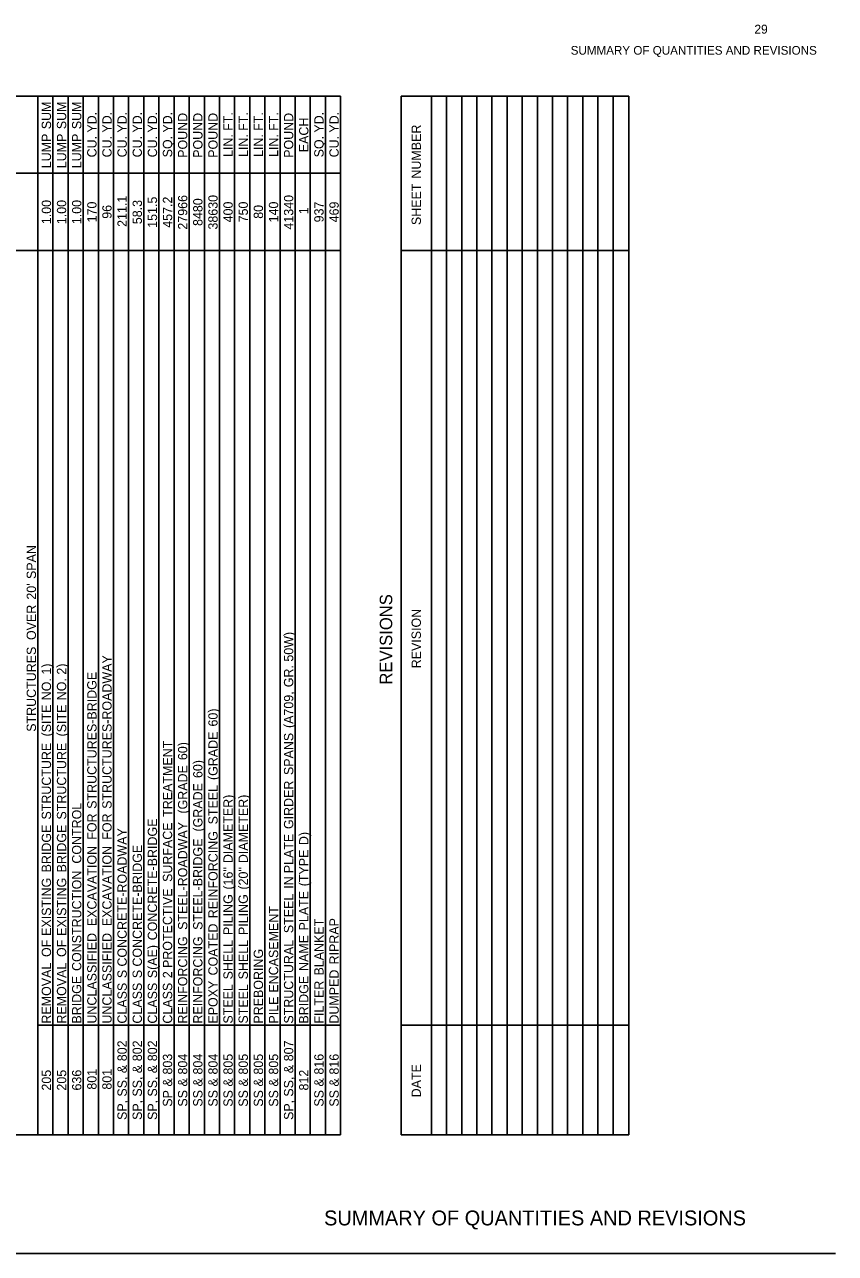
# Model space of a CAD drawing. Extents: x 1334737.6 to 1334769.2, y 402732.2 to 402752.
# Drawn here: x 1334756.13 to 1334769.18, y 402732.19 to 402751.98 of the extents above; entities that cross this region are included whole.
import ezdxf

# ---------------------------------------------------------------- set-up
doc = ezdxf.new("R2010")
doc.units = 0
doc.layers.add('Default', color=7, linetype='Continuous')
doc.layers.add('R_No Plot', color=7, linetype='Continuous')

msp = doc.modelspace()

# ---------------------------------------------------------------- linework, layer by layer
at = {"layer": 'Default'}
for p, q in [((1334761.215, 402750.83), (1334740.008, 402750.83)), ((1334756.34, 402734.097), (1334756.34, 402750.83)), ((1334756.583, 402734.097), (1334756.583, 402750.83)), ((1334756.827, 402734.097), (1334756.827, 402750.83)), ((1334757.071, 402734.097), (1334757.071, 402750.83)), ((1334757.315, 402734.097), (1334757.315, 402750.83)), ((1334757.558, 402734.097), (1334757.558, 402750.83)), ((1334757.802, 402734.097), (1334757.802, 402750.83)), ((1334758.046, 402734.097), (1334758.046, 402750.83)), ((1334758.29, 402734.097), (1334758.29, 402750.83)), ((1334758.533, 402734.097), (1334758.533, 402750.83)), ((1334758.777, 402734.097), (1334758.777, 402750.83)), ((1334759.021, 402734.097), (1334759.021, 402750.83)), ((1334759.265, 402734.097), (1334759.265, 402750.83)), ((1334759.508, 402734.097), (1334759.508, 402750.83)), ((1334759.752, 402734.097), (1334759.752, 402750.83)), ((1334759.996, 402734.097), (1334759.996, 402750.83)), ((1334760.24, 402734.097), (1334760.24, 402750.83)), ((1334760.483, 402734.097), (1334760.483, 402750.83)), ((1334760.727, 402734.097), (1334760.727, 402750.83)), ((1334760.971, 402734.097), (1334760.971, 402750.83)), ((1334761.215, 402734.097), (1334761.215, 402750.83)), ((1334762.19, 402734.097), (1334762.19, 402750.83)), ((1334762.19, 402748.344), (1334762.19, 402750.83)), ((1334765.858, 402750.83), (1334762.19, 402750.83)), ((1334762.677, 402734.097), (1334762.677, 402750.83)), ((1334762.921, 402734.097), (1334762.921, 402750.83)), ((1334763.165, 402734.097), (1334763.165, 402750.83)), ((1334763.408, 402734.097), (1334763.408, 402750.83)), ((1334763.652, 402734.097), (1334763.652, 402750.83)), ((1334763.896, 402734.097), (1334763.896, 402750.83)), ((1334764.14, 402734.097), (1334764.14, 402750.83)), ((1334764.383, 402734.097), (1334764.383, 402750.83)), ((1334764.627, 402734.097), (1334764.627, 402750.83)), ((1334764.871, 402734.097), (1334764.871, 402750.83)), ((1334765.115, 402734.097), (1334765.115, 402750.83)), ((1334765.358, 402734.097), (1334765.358, 402750.83)), ((1334765.602, 402734.097), (1334765.602, 402750.83)), ((1334765.858, 402734.097), (1334765.858, 402750.83)), ((1334761.215, 402749.587), (1334740.008, 402749.587)), ((1334761.215, 402749.587), (1334756.34, 402749.587)), ((1334761.215, 402748.344), (1334740.008, 402748.344)), ((1334761.215, 402748.344), (1334756.34, 402748.344)), ((1334762.677, 402748.344), (1334762.19, 402748.344)), ((1334765.858, 402748.344), (1334762.19, 402748.344)), ((1334757.071, 402735.864), (1334756.34, 402735.864)), ((1334761.215, 402735.864), (1334756.34, 402735.864)), ((1334762.19, 402734.097), (1334762.19, 402735.864)), ((1334765.858, 402735.864), (1334762.19, 402735.864)), ((1334761.215, 402734.097), (1334740.008, 402734.097)), ((1334765.858, 402734.097), (1334762.19, 402734.097))]:
    msp.add_line(p, q, dxfattribs=at)
at = {"layer": 'R_No Plot'}
msp.add_line((1334769.182, 402732.187), (1334737.564, 402732.187), dxfattribs=at)

# ---------------------------------------------------------------- texts
at = {"layer": 'Default'}
for s, height, p in [(' SUM', 0.15, (1334756.553, 402750.241)), (' SUM', 0.15, (1334756.797, 402750.241)), (' SUM', 0.15, (1334757.041, 402750.241)), (' YD.', 0.15, (1334757.285, 402750.186)), (' YD.', 0.15, (1334757.528, 402750.186)), (' YD.', 0.15, (1334757.772, 402750.186)), (' YD.', 0.15, (1334758.016, 402750.186)), (' YD.', 0.15, (1334758.26, 402750.186)), (' YD.', 0.15, (1334758.503, 402750.186)), ('POUND', 0.15, (1334758.747, 402749.836)), ('POUND', 0.15, (1334758.991, 402749.836)), ('POUND', 0.15, (1334759.235, 402749.836)), (' FT.', 0.15, (1334759.478, 402750.215)), (' FT.', 0.15, (1334759.722, 402750.215)), (' FT.', 0.15, (1334759.966, 402750.215)), (' FT.', 0.15, (1334760.21, 402750.215)), ('POUND', 0.15, (1334760.453, 402749.836)), (' YD.', 0.15, (1334760.941, 402750.186)), (' YD.', 0.15, (1334761.185, 402750.186)), ('EACH', 0.15, (1334760.697, 402749.926)), (' NUMBER', 0.15, (1334762.508, 402749.446)), ('LUMP', 0.15, (1334756.553, 402749.668)), ('LUMP', 0.15, (1334756.797, 402749.668)), ('LUMP', 0.15, (1334757.041, 402749.668)), ('CU.', 0.15, (1334757.285, 402749.843)), ('CU.', 0.15, (1334757.528, 402749.843)), ('CU.', 0.15, (1334757.772, 402749.843)), ('CU.', 0.15, (1334758.016, 402749.843)), ('CU.', 0.15, (1334758.26, 402749.843)), ('SQ.', 0.15, (1334758.503, 402749.843)), ('LIN.', 0.15, (1334759.478, 402749.849)), ('LIN.', 0.15, (1334759.722, 402749.849)), ('LIN.', 0.15, (1334759.966, 402749.849)), ('LIN.', 0.15, (1334760.21, 402749.849)), ('SQ.', 0.15, (1334760.941, 402749.843)), ('CU.', 0.15, (1334761.185, 402749.843)), ('SHEET', 0.15, (1334762.508, 402748.752)), ('211.1', 0.15, (1334757.772, 402748.723)), ('151.5', 0.15, (1334758.26, 402748.708)), ('457.2', 0.15, (1334758.503, 402748.709)), ('27966', 0.15, (1334758.747, 402748.679)), ('8480', 0.15, (1334758.991, 402748.738)), ('38630', 0.15, (1334759.235, 402748.68)), ('41340', 0.15, (1334760.453, 402748.68)), ('1.00', 0.15, (1334756.553, 402748.767)), ('1.00', 0.15, (1334756.797, 402748.767)), ('1.00', 0.15, (1334757.041, 402748.767)), ('170', 0.15, (1334757.285, 402748.796)), ('96', 0.15, (1334757.528, 402748.854)), ('58.3', 0.15, (1334758.016, 402748.767)), ('400', 0.15, (1334759.478, 402748.796)), ('750', 0.15, (1334759.722, 402748.796)), ('80', 0.15, (1334759.966, 402748.854)), ('140', 0.15, (1334760.21, 402748.796)), ('1', 0.15, (1334760.697, 402748.927)), ('937', 0.15, (1334760.941, 402748.796)), ('469', 0.15, (1334761.185, 402748.796)), (' SPAN', 0.15, (1334756.31, 402742.995)), (" 20'", 0.15, (1334756.31, 402742.663)), (' OVER', 0.15, (1334756.31, 402742.012)), ('REVISIONS', 0.2, (1334762.046, 402741.35)), ('REVISION', 0.15, (1334762.508, 402741.612)), (' 50W)', 0.15, (1334760.453, 402741.664)), ('STRUCTURES', 0.15, (1334756.31, 402740.59)), (' 1)', 0.15, (1334756.553, 402741.455)), (' 2)', 0.15, (1334756.797, 402741.455)), (' STRUCTURES-ROADWAY', 0.15, (1334757.528, 402739.293)), (' GR.', 0.15, (1334760.453, 402741.252)), (' NO.', 0.15, (1334756.553, 402741.042)), (' NO.', 0.15, (1334756.797, 402741.042)), (' STRUCTURES-BRIDGE', 0.15, (1334757.285, 402739.293)), (' (A709,', 0.15, (1334760.453, 402740.595)), (' (SITE', 0.15, (1334756.553, 402740.459)), (' (SITE', 0.15, (1334756.797, 402740.459)), (' 60)', 0.15, (1334759.235, 402740.619)), (' TREATMENT', 0.15, (1334758.503, 402739.164)), (' (GRADE', 0.15, (1334759.235, 402739.757)), (' SPANS', 0.15, (1334760.453, 402739.837)), (' STRUCTURE', 0.15, (1334756.553, 402739.12)), (' STRUCTURE', 0.15, (1334756.797, 402739.12)), (' 60)', 0.15, (1334758.747, 402740.078)), (' 60)', 0.15, (1334758.991, 402739.789)), (' (GRADE', 0.15, (1334758.747, 402739.216)), (' (GRADE', 0.15, (1334758.991, 402738.927)), (' STEEL', 0.15, (1334759.235, 402739.042)), (' GIRDER', 0.15, (1334760.453, 402738.967)), (' DIAMETER)', 0.15, (1334759.478, 402738.418)), (' DIAMETER)', 0.15, (1334759.722, 402738.418)), (' CONTROL', 0.15, (1334757.041, 402738.41)), (' FOR', 0.15, (1334757.285, 402738.795)), (' FOR', 0.15, (1334757.528, 402738.795)), (' BRIDGE', 0.15, (1334756.553, 402738.269)), (' BRIDGE', 0.15, (1334756.797, 402738.269)), (' CONCRETE-BRIDGE', 0.15, (1334758.26, 402737.175)), (' SURFACE', 0.15, (1334758.503, 402738.115)), (' STEEL-ROADWAY', 0.15, (1334758.747, 402737.343)), (' CONCRETE-ROADWAY', 0.15, (1334757.772, 402736.752)), (' STEEL-BRIDGE', 0.15, (1334758.991, 402737.343)), (' REINFORCING', 0.15, (1334759.235, 402737.53)), (' PLATE', 0.15, (1334760.453, 402738.256)), (' D)', 0.15, (1334760.697, 402738.709)), (' EXCAVATION', 0.15, (1334757.285, 402737.403)), (' EXCAVATION', 0.15, (1334757.528, 402737.403)), (' CONCRETE-BRIDGE', 0.15, (1334758.016, 402736.752)), (' (TYPE', 0.15, (1334760.697, 402738.045)), (' CONSTRUCTION', 0.15, (1334757.041, 402736.681)), (' (16"', 0.15, (1334759.478, 402737.992)), (' (20"', 0.15, (1334759.722, 402737.992)), (' EXISTING', 0.15, (1334756.553, 402737.246)), (' EXISTING', 0.15, (1334756.797, 402737.246)), (' IN', 0.15, (1334760.453, 402738.005)), (' PROTECTIVE', 0.15, (1334758.503, 402736.729)), (' PILING', 0.15, (1334759.478, 402737.26)), (' PILING', 0.15, (1334759.722, 402737.26)), (' STEEL', 0.15, (1334760.453, 402737.29)), (' PLATE', 0.15, (1334760.697, 402737.334)), (' ENCASEMENT', 0.15, (1334760.21, 402736.332)), (' COATED', 0.15, (1334759.235, 402736.609)), (' BLANKET', 0.15, (1334760.941, 402736.608)), (' RIPRAP', 0.15, (1334761.185, 402736.786)), ('UNCLASSIFIED', 0.15, (1334757.285, 402735.889)), ('UNCLASSIFIED', 0.15, (1334757.528, 402735.889)), ('REINFORCING', 0.15, (1334758.747, 402735.889)), ('REINFORCING', 0.15, (1334758.991, 402735.889)), (' NAME', 0.15, (1334760.697, 402736.681)), (' OF', 0.15, (1334756.553, 402736.906)), (' OF', 0.15, (1334756.797, 402736.906)), (' S(AE)', 0.15, (1334758.26, 402736.565)), (' SHELL', 0.15, (1334759.478, 402736.545)), (' SHELL', 0.15, (1334759.722, 402736.545)), ('PREBORING', 0.15, (1334759.966, 402735.889)), ('STRUCTURAL', 0.15, (1334760.453, 402735.889)), ('REMOVAL', 0.15, (1334756.553, 402735.889)), ('REMOVAL', 0.15, (1334756.797, 402735.889)), (' S', 0.15, (1334757.772, 402736.565)), (' S', 0.15, (1334758.016, 402736.565)), (' 2', 0.15, (1334758.503, 402736.565)), ('DUMPED', 0.15, (1334761.185, 402735.889)), ('BRIDGE', 0.15, (1334757.041, 402735.889)), ('CLASS', 0.15, (1334757.772, 402735.889)), ('CLASS', 0.15, (1334758.016, 402735.889)), ('CLASS', 0.15, (1334758.26, 402735.889)), ('CLASS', 0.15, (1334758.503, 402735.889)), ('EPOXY', 0.15, (1334759.235, 402735.889)), ('STEEL', 0.15, (1334759.478, 402735.889)), ('STEEL', 0.15, (1334759.722, 402735.889)), ('BRIDGE', 0.15, (1334760.697, 402735.889)), ('FILTER', 0.15, (1334760.941, 402735.889)), ('PILE', 0.15, (1334760.21, 402735.889)), (' 802', 0.15, (1334757.772, 402735.227)), (' 802', 0.15, (1334758.016, 402735.227)), (' 802', 0.15, (1334758.26, 402735.227)), (' 807', 0.15, (1334760.453, 402735.226)), (' 803', 0.15, (1334758.503, 402735.013)), (' 804', 0.15, (1334758.747, 402735.013)), (' 804', 0.15, (1334758.991, 402735.013)), (' 804', 0.15, (1334759.235, 402735.013)), (' 805', 0.15, (1334759.478, 402735.012)), (' 805', 0.15, (1334759.722, 402735.012)), (' 805', 0.15, (1334759.966, 402735.012)), (' 805', 0.15, (1334760.21, 402735.012)), (' 816', 0.15, (1334760.941, 402735.012)), (' 816', 0.15, (1334761.185, 402735.012)), ('205', 0.15, (1334756.553, 402734.81)), ('205', 0.15, (1334756.797, 402734.81)), ('636', 0.15, (1334757.041, 402734.811)), ('801', 0.15, (1334757.285, 402734.825)), ('801', 0.15, (1334757.528, 402734.825)), (' &', 0.15, (1334757.772, 402735.034)), (' &', 0.15, (1334758.016, 402735.034)), (' &', 0.15, (1334758.26, 402735.034)), (' &', 0.15, (1334760.453, 402735.033)), ('812', 0.15, (1334760.697, 402734.811)), ('DATE', 0.15, (1334762.508, 402734.701)), (' SS,', 0.15, (1334757.772, 402734.657)), (' SS,', 0.15, (1334758.016, 402734.657)), (' SS,', 0.15, (1334758.26, 402734.657)), (' &', 0.15, (1334758.503, 402734.82)), (' &', 0.15, (1334758.747, 402734.82)), (' &', 0.15, (1334758.991, 402734.82)), (' &', 0.15, (1334759.235, 402734.82)), (' &', 0.15, (1334759.478, 402734.819)), (' &', 0.15, (1334759.722, 402734.819)), (' &', 0.15, (1334759.966, 402734.819)), (' &', 0.15, (1334760.21, 402734.819)), (' SS,', 0.15, (1334760.453, 402734.656)), (' &', 0.15, (1334760.941, 402734.819)), (' &', 0.15, (1334761.185, 402734.819)), ('SP', 0.15, (1334758.503, 402734.55)), ('SS', 0.15, (1334758.747, 402734.551)), ('SS', 0.15, (1334758.991, 402734.551)), ('SS', 0.15, (1334759.235, 402734.551)), ('SS', 0.15, (1334759.478, 402734.55)), ('SS', 0.15, (1334759.722, 402734.55)), ('SS', 0.15, (1334759.966, 402734.55)), ('SS', 0.15, (1334760.21, 402734.55)), ('SS', 0.15, (1334760.941, 402734.551)), ('SS', 0.15, (1334761.185, 402734.551)), ('SP,', 0.15, (1334757.772, 402734.337)), ('SP,', 0.15, (1334758.016, 402734.337)), ('SP,', 0.15, (1334758.26, 402734.337)), ('SP,', 0.15, (1334760.453, 402734.337))]:
    msp.add_text(s, height=height, rotation=90, dxfattribs=at).set_placement(p)
at = {"layer": 'R_No Plot'}
for s, height, p in [('29', 0.1444, (1334767.878, 402751.836)), ('SUMMARY OF QUANTITIES AND REVISIONS', 0.24, (1334760.949, 402732.638))]:
    msp.add_text(s, height=height, dxfattribs=at).set_placement(p)
msp.add_text('SUMMARY OF QUANTITIES AND REVISIONS', height=0.14, rotation=360, dxfattribs=at).set_placement((1334764.92, 402751.497))

doc.saveas('drawing.dxf')
